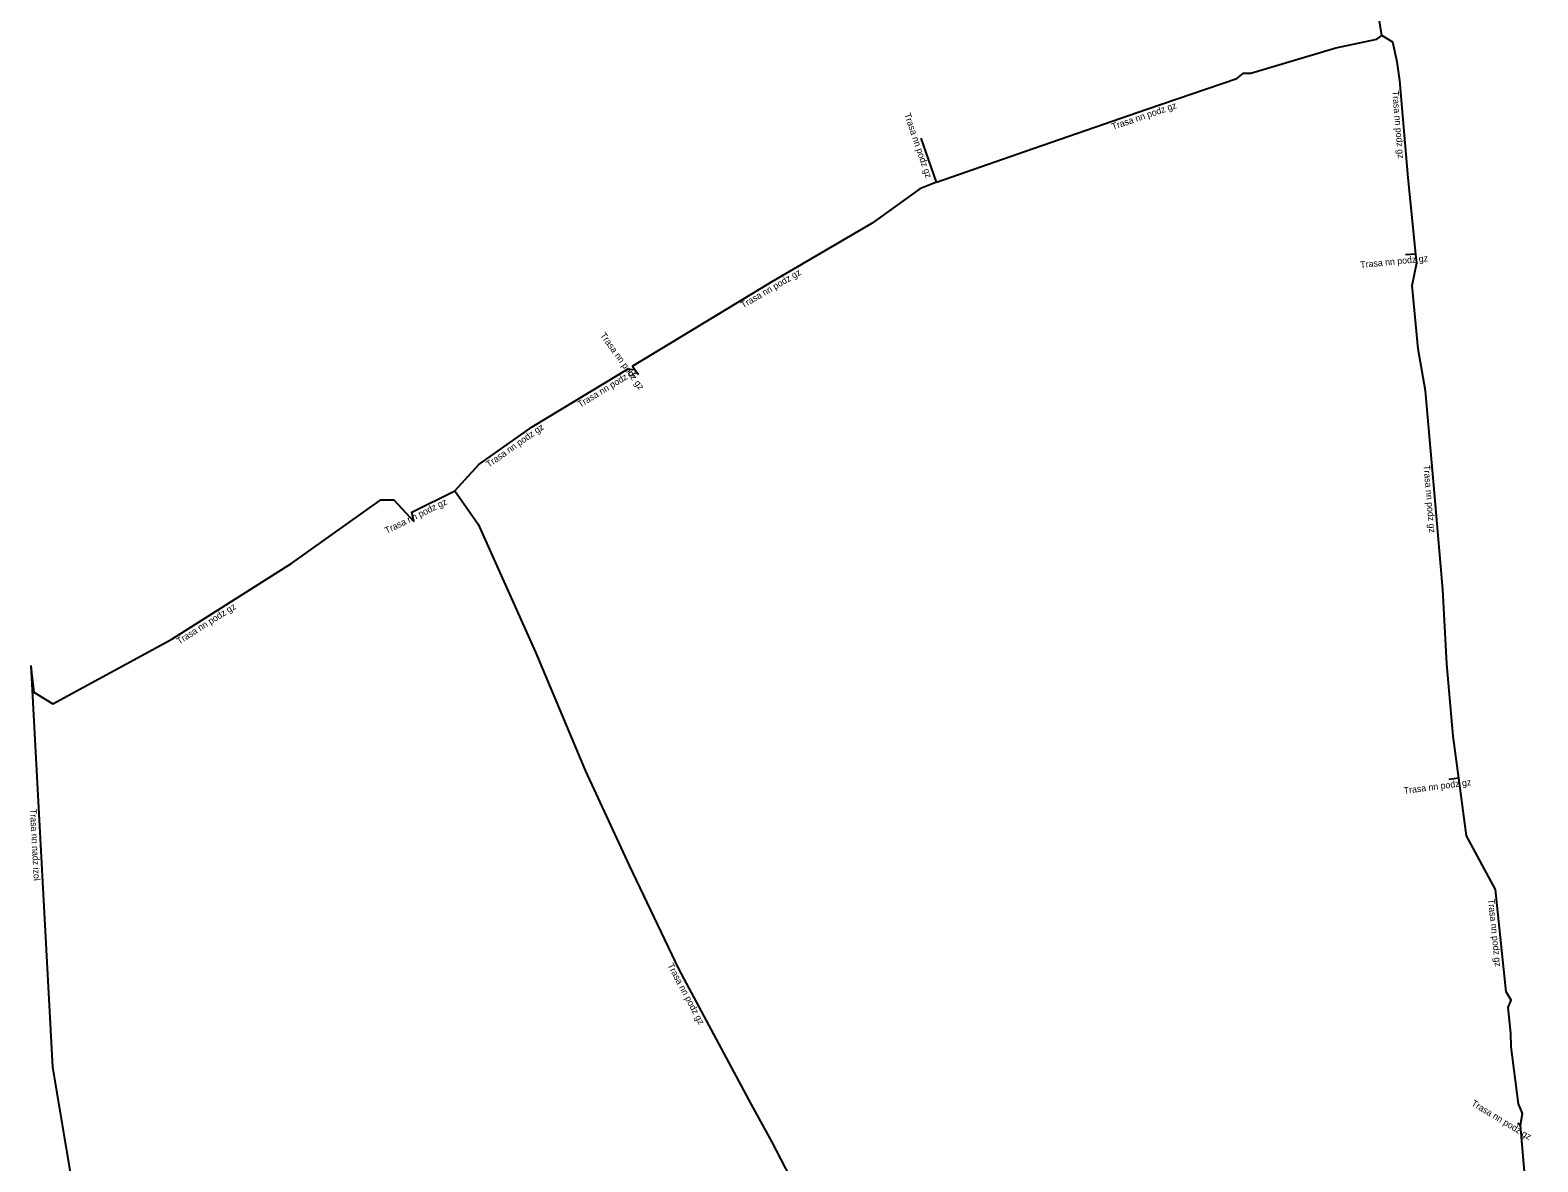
# Model space of a CAD drawing. Extents: x -745887 to -745704, y -1028211 to -1027575.
# Drawn here: x -745886.8 to -745772.3, y -1027811.5 to -1027725.5 of the extents above; entities that cross this region are included whole.
import ezdxf

# ---------------------------------------------------------------- set-up
doc = ezdxf.new("R2010")
doc.units = 0
doc.layers.add('Popiskový text - Ostatní atributy Trasy', color=7, linetype='Continuous')
doc.layers.add('Spojnice NN', color=7, linetype='Continuous')

msp = doc.modelspace()

# ---------------------------------------------------------------- linework, layer by layer
at = {"layer": 'Spojnice NN'}
for points in [[(-745784.12, -1027725.94), (-745784.8, -1027721.68)], [(-745817.97, -1027737.08), (-745811.19, -1027734.72), (-745801.98, -1027731.55), (-745795.14, -1027729.21), (-745794.64, -1027728.81), (-745794.07, -1027728.81), (-745787.62, -1027726.88), (-745784.5, -1027726.22), (-745784.12, -1027725.94)], [(-745781.53, -1027742.54), (-745782.11, -1027736.75), (-745782.75, -1027729.35), (-745782.94, -1027727.95), (-745783.27, -1027726.46), (-745784.12, -1027725.94)], [(-745817.97, -1027737.08), (-745819.12, -1027733.73)], [(-745817.97, -1027737.08), (-745819.23, -1027737.6), (-745822.86, -1027740.21), (-745830.48, -1027744.66), (-745839.92, -1027750.37), (-745841.06, -1027751.06), (-745840.89, -1027751.31)], [(-745781.53, -1027742.54), (-745782.32, -1027742.61)], [(-745778.27, -1027782.35), (-745778.69, -1027779.15), (-745779.18, -1027773.66), (-745779.49, -1027768.01), (-745780.16, -1027760.11), (-745780.79, -1027752.92), (-745781.35, -1027749.73), (-745781.81, -1027744.93), (-745781.46, -1027743.21), (-745781.53, -1027742.54)], [(-745843.12, -1027752.3), (-745841.44, -1027751.28), (-745840.89, -1027751.31)], [(-745840.89, -1027751.31), (-745840.61, -1027751.7)], [(-745854.57, -1027760.54), (-745852.73, -1027758.52), (-745848.69, -1027755.67), (-745843.12, -1027752.3)], [(-745886.78, -1027773.79), (-745886.73, -1027774.32), (-745886.56, -1027775.83), (-745885.11, -1027776.71), (-745876.07, -1027771.79), (-745866.95, -1027766.01), (-745860.18, -1027761.21), (-745859.19, -1027761.22), (-745857.68, -1027762.86)], [(-745857.68, -1027762.86), (-745857.68, -1027762.85), (-745857.82, -1027762.14), (-745854.57, -1027760.54)], [(-745854.57, -1027760.54), (-745852.79, -1027763.06), (-745848.43, -1027772.78), (-745844.64, -1027781.81), (-745841.31, -1027788.98), (-745837.53, -1027796.88), (-745832.04, -1027807.15), (-745830.5, -1027809.94), (-745828.02, -1027814.74), (-745824.1, -1027820.51), (-745820.33, -1027826.73), (-745819.57, -1027828.63), (-745817.89, -1027832.97), (-745816.2, -1027838.12)], [(-745886.78, -1027773.79), (-745885.15, -1027804.31)], [(-745778.27, -1027782.35), (-745779.02, -1027782.45)], [(-745773.59, -1027808.7), (-745773.43, -1027807.81), (-745773.73, -1027807.08), (-745774.29, -1027802.75), (-745774.31, -1027801.73), (-745774.52, -1027799.77), (-745774.29, -1027799.21), (-745774.66, -1027798.59), (-745775.48, -1027790.8), (-745777.69, -1027786.72), (-745778.27, -1027782.35)], [(-745885.15, -1027804.31), (-745879.39, -1027838.51)], [(-745773.59, -1027808.7), (-745773.79, -1027808.57)], [(-745772.26, -1027822.95), (-745772.4, -1027821.8), (-745773.14, -1027816.42), (-745773.06, -1027814.59), (-745773.59, -1027808.7)]]:
    msp.add_lwpolyline(points, dxfattribs=at)

# ---------------------------------------------------------------- texts
at = {"layer": 'Popiskový text - Ostatní atributy Trasy'}
for s, rotation, p in [('Trasa nn podz gz', 274.9239, (-745783.33, -1027730.16)), ('Trasa nn podz gz', 18.9163, (-745804.55, -1027733.12)), ('Trasa nn podz gz', 288.8494, (-745820.42, -1027731.93)), ('Trasa nn podz gz', 5.7751, (-745785.73, -1027743.61)), ('Trasa nn podz gz', 30.2817, (-745832.66, -1027746.68)), ('Trasa nn podz gz', 305.6764, (-745843.55, -1027748.72)), ('Trasa nn podz gz', 31.2637, (-745845.04, -1027754.22)), ('Trasa nn podz gz', 35.2371, (-745851.97, -1027758.78)), ('Trasa nn podz gz', 274.8639, (-745780.95, -1027758.59)), ('Trasa nn podz gz', 26.1259, (-745859.74, -1027763.8)), ('Trasa nn podz gz', 32.3731, (-745875.51, -1027772.21)), ('Trasa nn podz gz', 7.4703, (-745782.42, -1027783.55)), ('Trasa nn nadz izol', 273.0447, (-745886.85, -1027784.7)), ('Trasa nn podz gz', 275.9726, (-745776.05, -1027791.55)), ('Trasa nn podz gz', 298.1246, (-745838.43, -1027796.57)), ('Trasa nn podz gz', 328.9525, (-745777.36, -1027807.18))]:
    msp.add_text(s, height=0.5, rotation=rotation, dxfattribs=at).set_placement(p)

doc.saveas('drawing.dxf')
